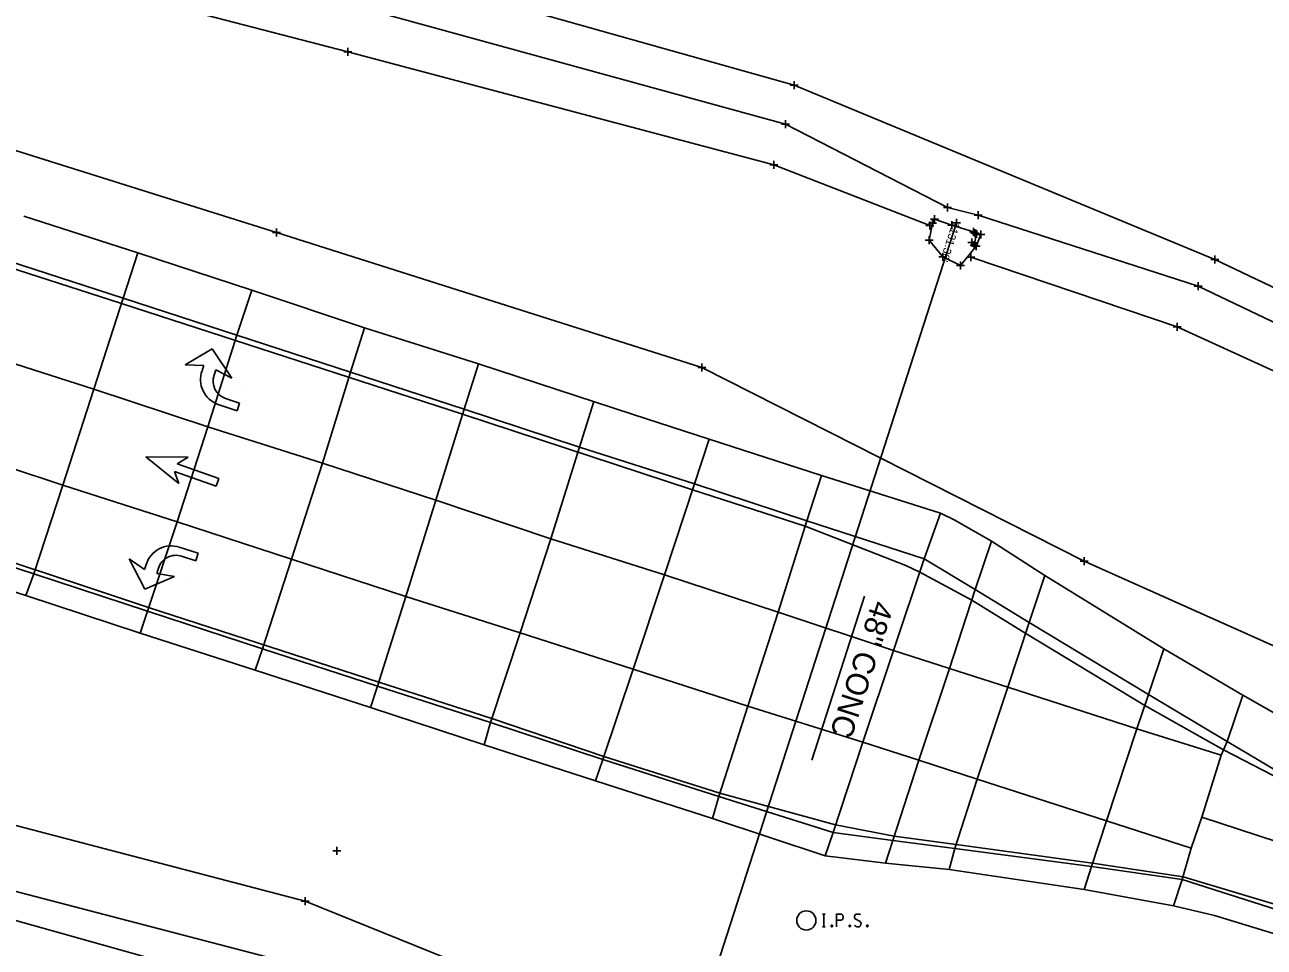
# Model space of a CAD drawing. Extents: x 207090 to 277928, y 600777 to 621109.
# Drawn here: x 261514.5 to 261669.3, y 612461.9 to 612577.2 of the extents above; entities that cross this region are included whole.
import ezdxf

# ---------------------------------------------------------------- set-up
doc = ezdxf.new("R2010")
doc.units = 0
for name, color, linetype in [('ATDIMS', 7, 'Continuous'), ('BR_X_SV_Abut', 7, 'Continuous'), ('DR_X_Ditch', 7, 'Continuous'), ('DR_X_Storm_Sewer', 7, 'Continuous'), ('DR_X_Text', 7, 'Continuous'), ('PM_P_Dotted_Line', 7, 'Continuous'), ('PM_P_Edge_Line', 7, 'Continuous'), ('PM_P_Stop_Line', 7, 'Continuous'), ('PM_X_Cells', 7, 'Continuous'), ('PM_X_Channelizing_Line', 7, 'Continuous'), ('PM_X_Edge_Line', 7, 'Continuous'), ('PV_X_EOP', 7, 'Continuous'), ('PV_X_Joint', 7, 'Continuous'), ('SC_ProfileRun2', 7, 'Continuous'), ('SV_X_Break_Lines', 7, 'Continuous'), ('SV_X_Toe_of_Slope', 7, 'Continuous')]:
    doc.layers.add(name, color=color, linetype=linetype)

msp = doc.modelspace()

# ---------------------------------------------------------------- linework, layer by layer
at = {"layer": 'BR_X_SV_Abut'}
msp.add_lwpolyline([(261633.15, 612551.13), (261633.38, 612551.06), (261633.08, 612549.66), (261632.78, 612549.97)], dxfattribs=at)
at = {"layer": 'DR_X_Ditch'}
for points in [[(261371.06, 612622.87), (261453.81, 612606.88), (261503.28, 612593.63), (261557.03, 612579.19), (261609.52, 612564.75), (261629.75, 612554.37), (261633.57, 612553.41), (261661.08, 612544.52), (261695.07, 612528.27), (261747.38, 612515.54), (261801.17, 612499.07), (261851.25, 612481.85), (261908.49, 612469.4), (261961.11, 612461.37), (262013.09, 612455.89), (262070.19, 612454.54), (262096.61, 612452.95), (262117.5, 612452.07), (262174.31, 612451.6)], [(261268.39, 612538.37), (261322.21, 612533.48), (261359.37, 612527.32), (261409.27, 612506.67), (261456.01, 612488.51), (261506.18, 612470.76), (261547.55, 612460), (261583.55, 612443.86), (261588.32, 612439.17), (261568.67, 612414.68), (261546.67, 612380.14)]]:
    msp.add_lwpolyline(points, dxfattribs=at)
at = {"layer": 'DR_X_Storm_Sewer'}
msp.add_line((261630.86, 612552.46), (261596.09, 612444.54), dxfattribs=at)
at = {"layer": 'DR_X_Text'}
msp.add_line((261612.8, 612485.31), (261619.4, 612505.8), dxfattribs=at)
at = {"layer": 'PM_P_Dotted_Line'}
for points in [[(261614.14, 612466.08), (261614.49, 612466.08)], [(261614.32, 612464.48), (261614.32, 612466.08)], [(261615.88, 612464.48), (261615.88, 612466.08), (261616.41, 612466.08), (261616.47, 612466.07), (261616.54, 612466.05), (261616.58, 612466.02), (261616.61, 612466), (261616.66, 612465.93), (261616.69, 612465.87), (261616.71, 612465.77), (261616.71, 612465.62), (261616.7, 612465.57), (261616.68, 612465.49), (261616.63, 612465.4), (261616.59, 612465.37), (261616.56, 612465.34), (261616.5, 612465.31), (261616.41, 612465.3), (261615.88, 612465.3)], [(261618.89, 612465.97), (261618.87, 612466), (261618.84, 612466.02), (261618.74, 612466.06), (261618.62, 612466.08), (261618.53, 612466.08), (261618.5, 612466.08), (261618.35, 612466.05), (261618.23, 612465.97), (261618.15, 612465.87), (261618.13, 612465.77), (261618.13, 612465.69), (261618.15, 612465.59), (261618.24, 612465.5), (261618.85, 612465.13), (261618.9, 612465.08), (261618.93, 612465.03), (261618.95, 612464.95), (261618.95, 612464.87), (261618.94, 612464.8), (261618.93, 612464.75), (261618.9, 612464.68), (261618.88, 612464.63), (261618.86, 612464.6), (261618.83, 612464.56), (261618.79, 612464.53), (261618.75, 612464.51), (261618.72, 612464.5), (261618.62, 612464.48), (261618.46, 612464.48), (261618.36, 612464.51), (261618.22, 612464.6), (261618.13, 612464.67)], [(261614.14, 612464.48), (261614.49, 612464.48)], [(261615.28, 612464.7), (261615.33, 612464.7), (261615.37, 612464.67), (261615.4, 612464.62), (261615.4, 612464.56), (261615.37, 612464.51), (261615.33, 612464.48), (261615.28, 612464.48), (261615.24, 612464.51), (261615.21, 612464.56), (261615.21, 612464.62), (261615.24, 612464.67), (261615.28, 612464.7)], [(261617.53, 612464.7), (261617.58, 612464.7), (261617.61, 612464.67), (261617.65, 612464.62), (261617.65, 612464.56), (261617.61, 612464.51), (261617.58, 612464.48), (261617.53, 612464.48), (261617.49, 612464.51), (261617.46, 612464.56), (261617.46, 612464.62), (261617.49, 612464.67), (261617.53, 612464.7)], [(261619.71, 612464.7), (261619.76, 612464.7), (261619.8, 612464.67), (261619.83, 612464.62), (261619.83, 612464.56), (261619.8, 612464.51), (261619.76, 612464.48), (261619.71, 612464.48), (261619.68, 612464.51), (261619.64, 612464.56), (261619.64, 612464.62), (261619.68, 612464.67), (261619.71, 612464.7)]]:
    msp.add_lwpolyline(points, dxfattribs=at)
msp.add_circle((261612.12, 612465.28), 1.2, dxfattribs=at)
at = {"layer": 'PM_P_Edge_Line'}
for points in [[(261153.15, 612627.77), (261169.13, 612620.58), (261181.76, 612617.43), (261224.75, 612615.38), (261257.04, 612605.54), (261311.09, 612603.38), (261371.54, 612597.09), (261444.06, 612581.8), (261497.27, 612566.51), (261545.93, 612551.25), (261599.05, 612534.38), (261646.81, 612510.16), (261684.07, 612493.5), (261735.89, 612477), (261791.89, 612460.55), (261844.51, 612443.55), (261901.19, 612426), (261956.82, 612413.77), (262012.19, 612405.94), (262069.02, 612401.45), (262118.25, 612399.35), (262173.21, 612399.21), (262230.21, 612398.82)], [(261263.47, 612539.83), (261269.01, 612541.34), (261322.02, 612535.23), (261361.19, 612530.5), (261411.17, 612512.95), (261459.12, 612494.16), (261509.03, 612478.25), (261549.54, 612467.7), (261586.92, 612452.56), (261598.14, 612450.56), (261607.22, 612446.03), (261595.95, 612434.69), (261570.84, 612412.62), (261554.87, 612384.32)], [(261263.33, 612539.26), (261268.28, 612536.81), (261321.23, 612530.7), (261357.06, 612521.5), (261408.09, 612502.78), (261453.99, 612483.63), (261504.43, 612467.79), (261545.99, 612456.09), (261581.09, 612437.96), (261545.67, 612388.85), (261542.67, 612378.86)]]:
    msp.add_lwpolyline(points, dxfattribs=at)
at = {"layer": 'PM_P_Stop_Line'}
for p, q in [((261554.34, 612573.8), (261555.34, 612573.8)), ((261554.84, 612574.3), (261554.84, 612573.3)), ((261554.84, 612573.8), (261554.84, 612573.8)), ((261610.09, 612569.65), (261611.09, 612569.65)), ((261610.59, 612570.15), (261610.59, 612569.15)), ((261610.59, 612569.65), (261610.59, 612569.65)), ((261609.02, 612564.75), (261610.02, 612564.75)), ((261609.52, 612565.25), (261609.52, 612564.25)), ((261609.52, 612564.75), (261609.52, 612564.75)), ((261607.57, 612559.7), (261608.57, 612559.7)), ((261608.07, 612560.2), (261608.07, 612559.2)), ((261608.07, 612559.7), (261608.07, 612559.7)), ((261629.25, 612554.37), (261630.25, 612554.37)), ((261629.75, 612554.87), (261629.75, 612553.87)), ((261629.75, 612554.37), (261629.75, 612554.37)), ((261633.57, 612553.91), (261633.57, 612552.91)), ((261627.06, 612552.1), (261628.06, 612552.1)), ((261627.4, 612552.4), (261628.4, 612552.4)), ((261627.56, 612552.6), (261627.56, 612551.6)), ((261627.56, 612552.1), (261627.56, 612552.1)), ((261627.62, 612552.9), (261628.62, 612552.9)), ((261627.9, 612552.9), (261627.9, 612551.9)), ((261627.9, 612552.4), (261627.9, 612552.4)), ((261628.12, 612553.4), (261628.12, 612552.4)), ((261628.12, 612552.9), (261628.12, 612552.9)), ((261629.78, 612552.15), (261630.78, 612552.15)), ((261630.28, 612552.65), (261630.28, 612551.65)), ((261630.28, 612552.15), (261630.28, 612552.15)), ((261633.07, 612553.41), (261634.07, 612553.41)), ((261633.57, 612553.41), (261633.57, 612553.41)), ((261545.43, 612551.25), (261546.43, 612551.25)), ((261545.93, 612551.75), (261545.93, 612550.75)), ((261545.93, 612551.25), (261545.93, 612551.25)), ((261627.48, 612550.77), (261627.48, 612549.77)), ((261632.5, 612551.32), (261633.5, 612551.32)), ((261632.65, 612551.13), (261633.65, 612551.13)), ((261632.78, 612550.47), (261632.78, 612549.47)), ((261632.88, 612551.06), (261633.88, 612551.06)), ((261633, 612551.82), (261633, 612550.82)), ((261633, 612551.32), (261633, 612551.32)), ((261633.15, 612551.63), (261633.15, 612550.63)), ((261633.15, 612551.13), (261633.15, 612551.13)), ((261633.38, 612551.56), (261633.38, 612550.56)), ((261633.38, 612551.06), (261633.38, 612551.06)), ((261633.41, 612550.97), (261634.41, 612550.97)), ((261633.91, 612551.47), (261633.91, 612550.47)), ((261633.91, 612550.97), (261633.91, 612550.97)), ((261626.98, 612550.27), (261627.98, 612550.27)), ((261627.48, 612550.27), (261627.48, 612550.27)), ((261632.28, 612549.97), (261633.28, 612549.97)), ((261632.58, 612549.66), (261633.58, 612549.66)), ((261632.78, 612549.97), (261632.78, 612549.97)), ((261632.83, 612549.54), (261633.83, 612549.54)), ((261633.08, 612550.16), (261633.08, 612549.16)), ((261633.08, 612549.66), (261633.08, 612549.66)), ((261633.33, 612550.04), (261633.33, 612549.04)), ((261633.33, 612549.54), (261633.33, 612549.54)), ((261628.68, 612548.2), (261629.68, 612548.2)), ((261629.18, 612548.7), (261629.18, 612547.7)), ((261629.18, 612548.2), (261629.18, 612548.2)), ((261631.36, 612547.6), (261631.36, 612546.6)), ((261632.17, 612548.15), (261633.17, 612548.15)), ((261632.67, 612548.65), (261632.67, 612547.65)), ((261632.67, 612548.15), (261632.67, 612548.15)), ((261662.66, 612547.85), (261663.66, 612547.85)), ((261663.16, 612548.35), (261663.16, 612547.35)), ((261663.16, 612547.85), (261663.16, 612547.85)), ((261630.86, 612547.1), (261631.86, 612547.1)), ((261631.36, 612547.1), (261631.36, 612547.1)), ((261660.58, 612544.52), (261661.58, 612544.52)), ((261661.08, 612545.02), (261661.08, 612544.02)), ((261661.08, 612544.52), (261661.08, 612544.52)), ((261658.46, 612539.95), (261658.46, 612538.95)), ((261657.96, 612539.45), (261658.96, 612539.45)), ((261658.46, 612539.45), (261658.46, 612539.45)), ((261599.05, 612534.88), (261599.05, 612533.88)), ((261598.55, 612534.38), (261599.55, 612534.38)), ((261599.05, 612534.38), (261599.05, 612534.38)), ((261646.31, 612510.16), (261647.31, 612510.16)), ((261646.81, 612510.66), (261646.81, 612509.66)), ((261646.81, 612510.16), (261646.81, 612510.16)), ((261549.04, 612467.7), (261550.04, 612467.7)), ((261549.54, 612468.2), (261549.54, 612467.2)), ((261549.54, 612467.7), (261549.54, 612467.7))]:
    msp.add_line(p, q, dxfattribs=at)
at = {"layer": 'PM_X_Cells'}
for p, q in [((261534.53, 612534.7), (261537.92, 612536.7)), ((261537.92, 612536.7), (261540.38, 612533.04)), ((261534.53, 612534.7), (261534.53, 612534.7)), ((261536.86, 612534.6), (261534.53, 612534.7)), ((261536.64, 612533.97), (261536.86, 612534.6)), ((261538.37, 612534.08), (261538.15, 612533.41)), ((261540.38, 612533.04), (261538.37, 612534.08)), ((261542.09, 612532.1), (261542.09, 612532.1)), ((261539.57, 612530.5), (261541.33, 612529.89)), ((261541.01, 612528.95), (261538.67, 612529.75)), ((261541.33, 612529.89), (261541.01, 612528.95)), ((261529.6, 612523.19), (261529.6, 612523.19)), ((261529.6, 612523.19), (261534.89, 612523.15)), ((261533.73, 612519.88), (261529.6, 612523.19)), ((261534.89, 612523.15), (261533.54, 612522.32)), ((261538.39, 612519.54), (261533.2, 612521.38)), ((261533.2, 612521.38), (261533.73, 612519.88)), ((261533.54, 612522.32), (261538.72, 612520.49)), ((261538.72, 612520.49), (261538.39, 612519.54)), ((261538.56, 612520.02), (261538.56, 612520.02)), ((261536.16, 612511.17), (261533.8, 612511.92)), ((261527.53, 612510.44), (261527.53, 612510.44)), ((261529.46, 612509.12), (261527.53, 612510.44)), ((261527.53, 612510.44), (261529.5, 612506.65)), ((261534.08, 612510.78), (261535.86, 612510.21)), ((261535.86, 612510.21), (261536.16, 612511.17)), ((261529.66, 612509.76), (261529.46, 612509.12)), ((261530.98, 612508.63), (261531.19, 612509.3)), ((261533.21, 612508.26), (261530.98, 612508.63)), ((261529.5, 612506.65), (261533.21, 612508.26)), ((261535.14, 612507.99), (261535.14, 612507.99))]:
    msp.add_line(p, q, dxfattribs=at)
for centre, radius, start, end in [((261539.73, 612532.85), 3.28, 160.1484, 251.0569), ((261540.32, 612532.67), 2.3, 161.0569, 251.0569), ((261532.8, 612508.8), 3.28, 72.1732, 163.0817), ((261533.38, 612508.6), 2.3, 72.1732, 162.1732)]:
    msp.add_arc(centre, radius, start, end, dxfattribs=at)
at = {"layer": 'PM_X_Channelizing_Line'}
for points in [[(261619.19, 612487.55), (261604.83, 612492.06), (261590.5, 612496.66), (261576.38, 612501.2), (261562.09, 612505.77), (261547.81, 612510.42), (261533.52, 612515.09), (261519.26, 612519.68), (261505.12, 612524.34), (261490.82, 612528.99), (261476.54, 612533.78), (261462.24, 612538.2), (261448.08, 612542.7), (261433.94, 612547.06), (261419.97, 612551.01), (261405.95, 612554.65), (261391.68, 612557.87), (261377.45, 612560.77), (261363.14, 612563.28)], [(261437.51, 612559.05), (261451.68, 612554.7), (261466.16, 612550.1), (261480.35, 612545.53), (261494.48, 612540.91), (261508.91, 612536.18), (261523.13, 612531.65), (261537.36, 612526.94), (261551.67, 612522.41), (261565.86, 612517.77), (261580.22, 612512.95), (261594.4, 612508.45), (261608.59, 612503.81), (261623.02, 612499)]]:
    msp.add_lwpolyline(points, dxfattribs=at)
at = {"layer": 'PM_X_Edge_Line'}
for points in [[(261352.04, 612588.86), (261381.61, 612583.93), (261411.35, 612577.56), (261440.7, 612569.65), (261469.59, 612560.69), (261497.91, 612551.61), (261526.56, 612542.38), (261569.19, 612528.53), (261597.9, 612519.09), (261611.97, 612514.53), (261624.55, 612509.61), (261626.3, 612508.78), (261632.78, 612505.3), (261639.52, 612501.13), (261654.4, 612492.14), (261664.22, 612486.59), (261670.44, 612483.38)], [(261673.1, 612466.55), (261659.17, 612470.73), (261647.86, 612472.43), (261630.84, 612474.76), (261623.11, 612475.82), (261615.78, 612477.23), (261601.33, 612481.17), (261586.83, 612485.75), (261572.85, 612490.5), (261558.73, 612495.06), (261529.97, 612504.39), (261501.77, 612513.75), (261487.46, 612518.3), (261458.85, 612527.66), (261444.81, 612532.03), (261430.82, 612536.24), (261403.3, 612543.66), (261389.31, 612546.89), (261375.42, 612549.65), (261361.43, 612552.25)]]:
    msp.add_lwpolyline(points, dxfattribs=at)
at = {"layer": 'PV_X_EOP'}
for points in [[(261673, 612489.82), (261666.65, 612493.41), (261656.79, 612499.23), (261641.93, 612508.38), (261635.24, 612512.65), (261630.66, 612515.31), (261628.86, 612516.17), (261614.01, 612520.87), (261599.97, 612525.4), (261590.47, 612528.51), (261580.96, 612531.62), (261571.16, 612534.82), (261556.95, 612539.34), (261542.84, 612544.03), (261528.61, 612548.68), (261514.36, 612553.29)], [(261671.98, 612463.2), (261663.12, 612465.9), (261657.99, 612467.1), (261646.83, 612469.16), (261629.98, 612471.65), (261621.99, 612472.44), (261614.48, 612473.35), (261600.4, 612478.01), (261585.77, 612482.71), (261571.89, 612487.21), (261557.7, 612491.88), (261543.29, 612496.57), (261528.93, 612501.18), (261514.64, 612505.87), (261500.75, 612510.34)]]:
    msp.add_lwpolyline(points, dxfattribs=at)
at = {"layer": 'PV_X_Joint'}
for points in [[(261671.16, 612483.8), (261664.67, 612487.64), (261654.86, 612493.5), (261639.97, 612502.49), (261633.22, 612506.64), (261626.85, 612510.44), (261612.19, 612515.22), (261598.14, 612519.81), (261583.8, 612524.42), (261569.38, 612529.16), (261555.19, 612533.77), (261540.99, 612538.41), (261526.77, 612543.03), (261512.56, 612547.64), (261498.13, 612552.31), (261484.03, 612556.87), (261469.83, 612561.45), (261455.09, 612566.21), (261440.94, 612570.44), (261426.29, 612574.7), (261411.56, 612578.5), (261396.96, 612581.79), (261381.78, 612584.88), (261366.96, 612587.49)], [(261365.17, 612575.68), (261379.71, 612573.26), (261394.42, 612570.23), (261408.88, 612566.97), (261423.21, 612563.09), (261437.51, 612559.05), (261451.68, 612554.7), (261466.16, 612550.1), (261480.35, 612545.53), (261494.48, 612540.91), (261508.91, 612536.18), (261523.13, 612531.65), (261537.36, 612526.94), (261551.67, 612522.41), (261565.86, 612517.77), (261580.22, 612512.95), (261594.4, 612508.45), (261608.59, 612503.81), (261623.02, 612499), (261629.99, 612496.75), (261637.27, 612494.41), (261653.41, 612489.22), (261663.93, 612485.92)], [(261363.22, 612563.79), (261377.55, 612561.32), (261391.8, 612558.42), (261406.08, 612555.17), (261420.11, 612551.56), (261434.09, 612547.57), (261448.21, 612543.13), (261462.37, 612538.59), (261476.54, 612533.78), (261490.82, 612528.99), (261505.12, 612524.34), (261519.26, 612519.68), (261533.52, 612515.09), (261547.81, 612510.42), (261562.09, 612505.77), (261576.38, 612501.2), (261590.5, 612496.66), (261604.83, 612492.06), (261619.19, 612487.55), (261626.17, 612485.3), (261633.45, 612482.92), (261649.6, 612477.74), (261660.19, 612474.31)], [(261361.37, 612551.88), (261375.37, 612549.38), (261389.26, 612546.62), (261403.25, 612543.43), (261416.98, 612539.7), (261430.7, 612535.83), (261444.68, 612531.59), (261458.69, 612527.16), (261472.87, 612522.51), (261487.29, 612517.77), (261501.58, 612513.13), (261515.62, 612508.57), (261529.81, 612503.93), (261544.19, 612499.22), (261558.57, 612494.55), (261572.69, 612490.01), (261586.72, 612485.4), (261601.21, 612480.78), (261615.47, 612476.28), (261622.93, 612475.26), (261630.69, 612474.28), (261647.72, 612472), (261659.07, 612470.38), (261672.9, 612465.97)], [(261528.61, 612548.68), (261526.77, 612543.03), (261523.13, 612531.65), (261519.26, 612519.68), (261515.62, 612508.57), (261514.64, 612505.87)], [(261528.93, 612501.18), (261529.81, 612503.93), (261533.52, 612515.09), (261537.36, 612526.94), (261540.99, 612538.41), (261542.84, 612544.03)], [(261556.95, 612539.34), (261555.19, 612533.77), (261551.67, 612522.41), (261547.81, 612510.42), (261544.19, 612499.22), (261543.29, 612496.57)], [(261557.7, 612491.88), (261558.57, 612494.55), (261562.09, 612505.77), (261565.86, 612517.77), (261569.38, 612529.16), (261571.16, 612534.82)], [(261571.89, 612487.21), (261572.69, 612490.01), (261576.38, 612501.2), (261580.22, 612512.95), (261583.8, 612524.42), (261585.56, 612530.11)], [(261599.97, 612525.4), (261598.14, 612519.81), (261594.4, 612508.45), (261590.5, 612496.66), (261586.72, 612485.4), (261585.77, 612482.71)], [(261600.4, 612478.01), (261601.21, 612480.78), (261604.83, 612492.06), (261608.59, 612503.81), (261612.19, 612515.22), (261614.01, 612520.87)], [(261628.86, 612516.17), (261626.85, 612510.44), (261623.02, 612499), (261619.19, 612487.55), (261615.47, 612476.28), (261614.48, 612473.35)], [(261621.99, 612472.44), (261622.93, 612475.26), (261626.17, 612485.3), (261629.99, 612496.75), (261633.22, 612506.64), (261635.24, 612512.65)], [(261641.93, 612508.38), (261639.97, 612502.49), (261637.27, 612494.41), (261633.45, 612482.92), (261630.69, 612474.28), (261629.98, 612471.65)], [(261646.83, 612469.16), (261647.72, 612472), (261649.6, 612477.74), (261653.41, 612489.22), (261654.86, 612493.5), (261656.79, 612499.23)], [(261666.65, 612493.41), (261664.67, 612487.64), (261663.93, 612485.92), (261661.54, 612478.19), (261660.19, 612474.31), (261659.07, 612470.38), (261657.99, 612467.1)], [(261661.54, 612478.19), (261675.52, 612473.6), (261689.68, 612468.96), (261704.17, 612464.23), (261718.45, 612459.53), (261732.74, 612454.89), (261747.01, 612450.28), (261761.15, 612445.67), (261775.38, 612441.01), (261789.54, 612436.4), (261803.82, 612431.78), (261818.03, 612427.14), (261832.4, 612422.45), (261846.76, 612417.89), (261861.25, 612413.48), (261876.02, 612409.31), (261890.74, 612405.43)]]:
    msp.add_lwpolyline(points, dxfattribs=at)
at = {"layer": 'SC_ProfileRun2'}
for p, q in [((261630.36, 612552.46), (261631.36, 612552.46)), ((261630.86, 612552.96), (261630.86, 612551.96)), ((261630.86, 612552.46), (261630.86, 612552.46)), ((261553.46, 612474.49), (261553.46, 612473.49)), ((261552.96, 612473.99), (261553.96, 612473.99)), ((261553.46, 612473.99), (261553.46, 612473.99))]:
    msp.add_line(p, q, dxfattribs=at)
at = {"layer": 'SV_X_Break_Lines'}
msp.add_lwpolyline([(261633, 612551.32), (261633.91, 612550.97), (261633.33, 612549.54), (261631.36, 612547.1), (261629.18, 612548.2), (261627.48, 612550.27), (261627.9, 612552.4), (261628.12, 612552.9), (261630.28, 612552.15)], close=True, dxfattribs=at)
at = {"layer": 'SV_X_Toe_of_Slope'}
for points in [[(261254.54, 612625.45), (261313.5, 612625.8), (261370.86, 612626.45), (261455.34, 612610.52), (261504.93, 612599.21), (261559.63, 612583.99), (261610.59, 612569.65), (261663.16, 612547.85), (261696.02, 612532.19), (261748.91, 612519.6), (261803, 612503.05), (261854.14, 612488.44), (261909.19, 612475.03), (261962.46, 612466.1), (262013.09, 612461.24), (262069.53, 612460.86), (262094.78, 612461.3), (262105.98, 612459.74), (262118.66, 612458.13), (262175.17, 612457.42), (262228.71, 612456.27)], [(261255.5, 612614.49), (261312.64, 612618.26), (261371.97, 612615.68), (261452.31, 612602.72), (261501.72, 612587.58), (261554.84, 612573.8), (261608.07, 612559.7), (261627.56, 612552.1)], [(261632.67, 612548.15), (261658.46, 612539.45), (261693.69, 612523.31), (261746.6, 612507.21), (261798.78, 612490.88), (261851.13, 612476.19), (261905.95, 612462.56), (261960.67, 612453.46), (262013.07, 612449.96), (262069.59, 612448.09), (262097.23, 612447.15), (262173.96, 612445.81), (262227.3, 612443.44)]]:
    msp.add_lwpolyline(points, dxfattribs=at)

# ---------------------------------------------------------------- texts
at = {"layer": 'ATDIMS'}
msp.add_text("1131.30'", height=1, rotation=252.1384, dxfattribs=at).set_placement((261630.39, 612552.61))
msp.add_text("1131.30'", height=1, rotation=252.1384, dxfattribs=at).set_placement((261630.39, 612552.61))
at = {"layer": 'DR_X_Text'}
msp.add_text('48" CONC', height=2.8, rotation=252.1384, dxfattribs=at).set_placement((261620.43, 612505.4))

doc.saveas('drawing.dxf')
